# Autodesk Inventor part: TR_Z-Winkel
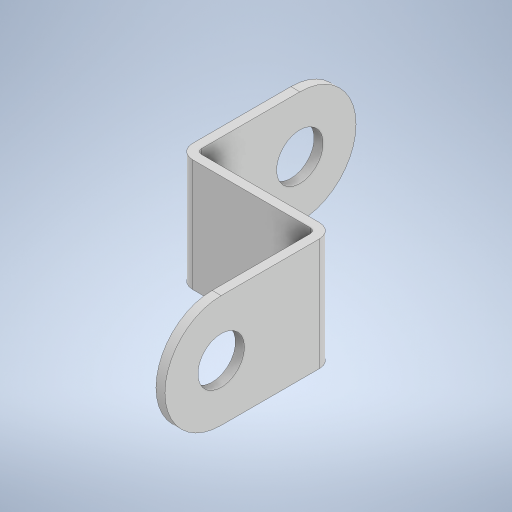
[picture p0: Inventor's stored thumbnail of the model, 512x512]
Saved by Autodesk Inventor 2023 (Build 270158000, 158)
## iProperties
Created: 2023-11
Part Number: TR_Z-Winkel
Material: Generisch
Document SubType Name: Modeling
Designer: Administrator
Density: 1 g/cm^3
Appearance: Vorgabe
Author: Administrator
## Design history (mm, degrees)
sketch "Skizze1"
  geometry: L1 (0, 0)-(0, -13.75); L2 (1.25, -15)-(11.75, -15); L3 (12.2, -15.45)-(12.2, -29.2); L4 (12.2, -29.2)-(13, -29.2); L5 (13, -29.2)-(13, -15.45); L6 (11.75, -14.2)-(1.25, -14.2); L7 (0.8, -13.75)-(0.8, 0); L8 (0.8, 0)-(0, 0); A1 r 1.25 centre (1.25, -13.75) between (0, -13.75) and (1.25, -15); A2 r 1.25 centre (11.75, -15.45) between (13, -15.45) and (11.75, -14.2); A3 r 0.45 centre (11.75, -15.45) between (12.2, -15.45) and (11.75, -15); A4 r 0.45 centre (1.25, -13.75) between (0.8, -13.75) and (1.25, -14.2)
  constraints: 16 end point, 8 point on circle, 8 tangent, 5 perpendicular, 4 centre point, 2 coincident, 2 equal radius, 2 parallel, 1 horizontal, 1 vertical
  dimensions: "d0" = 0.8 distance between parallel lines of L1 L7; "d1" = 1.25 radius of A1; "d4" = 15 vertical distance of L2.start L7.end; "d5" = 13 distance between parallel lines of L1 L5
extrude "Extrusion1" new body sketch "Skizze1" stored distance "d6" = 10 (= Einheitsmaß); taper "d7" = 0 deg
fillet "Rundung1" dims "d8" = 5 (= 0.5 x Einheitsmaß)
sketch "Skizze2"
  geometry: C1 r 2.075 at (-8.75, 5); C2 r 2.075 at (10.45, 5); A1 r 5 centre (-8.75, 5) between (-8.75, 10) and (-8.75, 0) reference; A2 r 5 centre (10.45, 5) between (10.45, 0) and (10.45, 10) reference; 1 further point
  constraints: 2 centre point, 2 coincident
  dimensions: "d9" = 4.15 diameter of C1 (= 2 x Radius); "d10" = 4.15 diameter of C2 (= 2 x Radius)
extrude "Extrusion2" cut sketch "Skizze2" extent not by distance; stored distance "d11" = 0; taper "d12" = 0 deg
node "Volumenkörper1"
other parameters: "Einheitsmaß" = 10 [user parameter; used in 2 equation terms], "Radius" = 2.075 [user parameter; used in 2 equation terms], "Fasen" = 0.5 [user parameter], "Dicke" = 0.8 [user parameter], "Breitloch" = 2 [user parameter], "Langloch" = 32 [user parameter], "AchteckUmkreis" = 6 [user parameter], "DAchsAufnahme" = 4.1 [user parameter], "AchsDurchmesser" = 4 [user parameter], "AchsFase" = 0.5 [user parameter]
